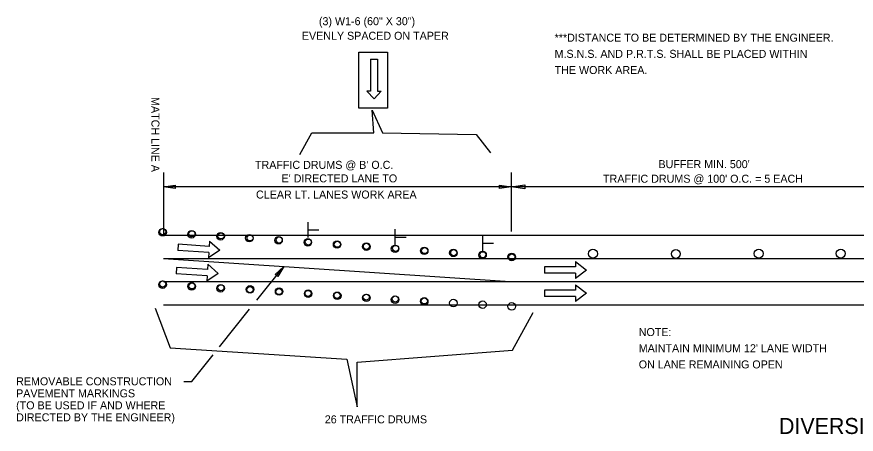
# Model space of a CAD drawing. Extents: x 1373848 to 1374003, y 380642 to 381248.
# Drawn here: x 1373852.3 to 1373915.2, y 381154.8 to 381186.1 of the extents above; entities that cross this region are included whole.
import ezdxf

# ---------------------------------------------------------------- set-up
doc = ezdxf.new("R2010")
doc.units = 0
doc.layers.add('Default', color=7, linetype='Continuous')

msp = doc.modelspace()

# ---------------------------------------------------------------- linework, layer by layer
at = {"layer": 'Default'}
for p, q in [((1373878.817, 381182.957), (1373878.817, 381180.567)), ((1373878.817, 381182.957), (1373879.349, 381182.957)), ((1373879.349, 381182.957), (1373879.349, 381180.567)), ((1373878.817, 381180.567), (1373878.551, 381180.567)), ((1373878.551, 381180.567), (1373879.083, 381179.983)), ((1373879.083, 381179.983), (1373879.616, 381180.567)), ((1373879.349, 381180.567), (1373879.616, 381180.567)), ((1373863.296, 381174.476), (1373863.296, 381170.048)), ((1373889.355, 381174.476), (1373889.355, 381170.048)), ((1373863.296, 381173.398), (1373864.166, 381173.528)), ((1373889.355, 381173.398), (1373863.296, 381173.398)), ((1373864.166, 381173.267), (1373863.296, 381173.398)), ((1373864.166, 381173.528), (1373864.166, 381173.267)), ((1373888.485, 381173.267), (1373888.485, 381173.528)), ((1373888.485, 381173.528), (1373889.355, 381173.398)), ((1373889.355, 381173.398), (1373888.485, 381173.267)), ((1373889.355, 381173.398), (1373890.385, 381173.552)), ((1373920.265, 381173.398), (1373889.355, 381173.398)), ((1373890.385, 381173.243), (1373889.355, 381173.398)), ((1373890.385, 381173.552), (1373890.385, 381173.243)), ((1373863.296, 381172.953), (1373863.296, 381169.76)), ((1373874.136, 381169.59), (1373874.136, 381170.751)), ((1373874.153, 381170.168), (1373874.946, 381170.168)), ((1373880.678, 381169.048), (1373880.678, 381170.21)), ((1373863.296, 381169.76), (1373889.374, 381169.76)), ((1373866.749, 381169.322), (1373866.723, 381168.927)), ((1373866.749, 381169.322), (1373867.526, 381168.636)), ((1373880.695, 381169.626), (1373881.487, 381169.626)), ((1373887.234, 381168.597), (1373887.234, 381169.759)), ((1373889.374, 381169.76), (1373916.267, 381169.76)), ((1373864.403, 381169.083), (1373864.371, 381168.61)), ((1373866.691, 381168.454), (1373864.371, 381168.61)), ((1373866.723, 381168.927), (1373864.403, 381169.083)), ((1373867.526, 381168.636), (1373866.665, 381168.06)), ((1373887.251, 381169.175), (1373888.044, 381169.175)), ((1373863.296, 381168.022), (1373889.284, 381168.022)), ((1373863.296, 381168.022), (1373889.284, 381166.283)), ((1373866.691, 381168.454), (1373866.665, 381168.06)), ((1373889.284, 381168.022), (1373916.485, 381168.022)), ((1373864.287, 381167.348), (1373864.255, 381166.875)), ((1373866.607, 381167.193), (1373864.287, 381167.348)), ((1373866.633, 381167.587), (1373866.607, 381167.193)), ((1373866.633, 381167.587), (1373867.41, 381166.901)), ((1373871.668, 381166.82), (1373872.311, 381167.419)), ((1373872.311, 381167.419), (1373871.872, 381166.658)), ((1373894.185, 381167.39), (1373891.859, 381167.39)), ((1373891.859, 381167.39), (1373891.859, 381166.915)), ((1373894.185, 381167.785), (1373894.185, 381167.39)), ((1373894.185, 381167.785), (1373895.005, 381167.153)), ((1373866.575, 381166.72), (1373864.255, 381166.875)), ((1373867.41, 381166.901), (1373866.549, 381166.325)), ((1373866.575, 381166.72), (1373866.549, 381166.325)), ((1373871.872, 381166.658), (1373871.668, 381166.82)), ((1373894.185, 381166.915), (1373891.859, 381166.915)), ((1373895.005, 381167.153), (1373894.185, 381166.52)), ((1373894.185, 381166.915), (1373894.185, 381166.52)), ((1373863.296, 381166.283), (1373889.284, 381166.283)), ((1373889.284, 381166.283), (1373916.485, 381166.283)), ((1373894.185, 381165.651), (1373891.859, 381165.651)), ((1373891.859, 381165.651), (1373891.859, 381165.177)), ((1373894.185, 381166.046), (1373894.185, 381165.651)), ((1373894.185, 381166.046), (1373895.005, 381165.414)), ((1373894.185, 381165.177), (1373891.859, 381165.177)), ((1373895.005, 381165.414), (1373894.185, 381164.782)), ((1373894.185, 381165.177), (1373894.185, 381164.782)), ((1373863.296, 381164.545), (1373889.333, 381164.545)), ((1373889.333, 381164.545), (1373916.839, 381164.545))]:
    msp.add_line(p, q, dxfattribs=at)
msp.add_lwpolyline([(1373877.941, 381179.3), (1373877.941, 381183.492), (1373880.085, 381183.492), (1373880.085, 381179.3)], close=True, dxfattribs=at)
for points in [[(1373873.532, 381175.815), (1373874.432, 381177.445), (1373879.056, 381177.445), (1373878.935, 381179.133), (1373879.716, 381177.445), (1373886.741, 381177.328), (1373887.821, 381175.931)], [(1373870.291, 381164.884), (1373872.311, 381167.419)], [(1373862.675, 381164.3), (1373863.802, 381161.309), (1373877.054, 381160.46), (1373877.806, 381156.886), (1373877.806, 381160.241), (1373889.454, 381161.145), (1373891.008, 381163.978)], [(1373867.503, 381161.384), (1373869.76, 381164.218)], [(1373864.818, 381158.782), (1373865.429, 381158.782), (1373867.022, 381160.781)]]:
    msp.add_lwpolyline(points, dxfattribs=at)
for centre, radius in [((1373863.238, 381169.986), 0.281), ((1373863.238, 381170.031), 0.229), ((1373863.25, 381170.03), 0.229), ((1373865.411, 381169.833), 0.281), ((1373865.431, 381169.873), 0.229), ((1373867.584, 381169.681), 0.281), ((1373867.612, 381169.715), 0.229), ((1373869.732, 381169.544), 0.281), ((1373869.792, 381169.558), 0.229), ((1373871.926, 381169.385), 0.281), ((1373871.973, 381169.4), 0.229), ((1373874.12, 381169.226), 0.281), ((1373874.154, 381169.243), 0.229), ((1373876.314, 381169.066), 0.281), ((1373876.334, 381169.085), 0.229), ((1373878.508, 381168.907), 0.281), ((1373878.515, 381168.928), 0.229), ((1373880.657, 381168.742), 0.281), ((1373880.696, 381168.77), 0.229), ((1373882.844, 381168.59), 0.281), ((1373882.876, 381168.612), 0.229), ((1373885.031, 381168.437), 0.281), ((1373885.057, 381168.455), 0.229), ((1373895.49, 381168.375), 0.333), ((1373901.704, 381168.36), 0.333), ((1373907.918, 381168.381), 0.333), ((1373914.066, 381168.383), 0.333), ((1373887.218, 381168.285), 0.281), ((1373887.238, 381168.297), 0.229), ((1373889.405, 381168.132), 0.281), ((1373889.406, 381168.141), 0.229), ((1373889.418, 381168.14), 0.229), ((1373863.238, 381166.059), 0.281), ((1373863.238, 381166.104), 0.229), ((1373863.25, 381166.103), 0.229), ((1373865.411, 381165.92), 0.281), ((1373865.428, 381165.962), 0.229), ((1373867.584, 381165.781), 0.281), ((1373867.606, 381165.821), 0.229), ((1373869.788, 381165.7), 0.281), ((1373869.784, 381165.68), 0.229), ((1373871.968, 381165.541), 0.281), ((1373871.962, 381165.539), 0.229), ((1373874.148, 381165.382), 0.281), ((1373874.139, 381165.398), 0.229), ((1373876.328, 381165.222), 0.281), ((1373876.317, 381165.257), 0.229), ((1373878.508, 381165.063), 0.281), ((1373878.495, 381165.116), 0.229), ((1373880.657, 381164.926), 0.281), ((1373880.673, 381164.975), 0.229), ((1373882.844, 381164.801), 0.281), ((1373882.851, 381164.834), 0.229), ((1373885.031, 381164.676), 0.281), ((1373887.218, 381164.552), 0.281), ((1373889.405, 381164.427), 0.281)]:
    msp.add_circle(centre, radius, dxfattribs=at)

# ---------------------------------------------------------------- texts
for s, rotation, p in [('(3) W1-6 (60" X 30")', 0.00754, (1373874.951, 381185.512)), ('EVENLY SPACED ON TAPER', 0.00754, (1373873.673, 381184.42)), ('***DISTANCE TO BE DETERMINED BY THE ENGINEER.', 360, (1373892.618, 381184.278)), ('M.S.N.S. AND P.R.T.S. SHALL BE PLACED WITHIN', 360, (1373892.618, 381183.065)), ('THE WORK AREA.', 360, (1373892.618, 381181.852)), ('MATCH LINE A', 270, (1373862.396, 381180.125))]:
    msp.add_text(s, height=0.6, rotation=rotation, dxfattribs=at).set_placement(p)
for s, height, p in [("TRAFFIC DRUMS @ B' O.C.", 0.6, (1373870.158, 381174.739)), ("BUFFER MIN. 500'", 0.6, (1373900.402, 381174.791)), ("E' DIRECTED LANE TO", 0.6, (1373872.15, 381173.725)), ("TRAFFIC DRUMS @ 100' O.C. = 5 EACH", 0.6, (1373896.247, 381173.699)), ('CLEAR LT. LANES WORK AREA', 0.6, (1373870.237, 381172.512)), ('NOTE:', 0.6, (1373898.924, 381162.199)), ("MAINTAIN MINIMUM 12' LANE WIDTH", 0.6, (1373898.924, 381160.986)), ('ON LANE REMAINING OPEN', 0.6, (1373898.924, 381159.773)), ('REMOVABLE CONSTRUCTION', 0.6, (1373852.256, 381158.504)), ('PAVEMENT MARKINGS', 0.6, (1373852.256, 381157.604)), ('(TO BE USED IF AND WHERE', 0.6, (1373852.256, 381156.704)), ('DIRECTED BY THE ENGINEER)', 0.6, (1373852.256, 381155.804)), ('26 TRAFFIC DRUMS', 0.6, (1373875.391, 381155.652)), ('DIVERSION FOR LT. LANE WORK ZONE', 1.2, (1373909.435, 381154.854))]:
    msp.add_text(s, height=height, dxfattribs=at).set_placement(p)

doc.saveas('drawing.dxf')
